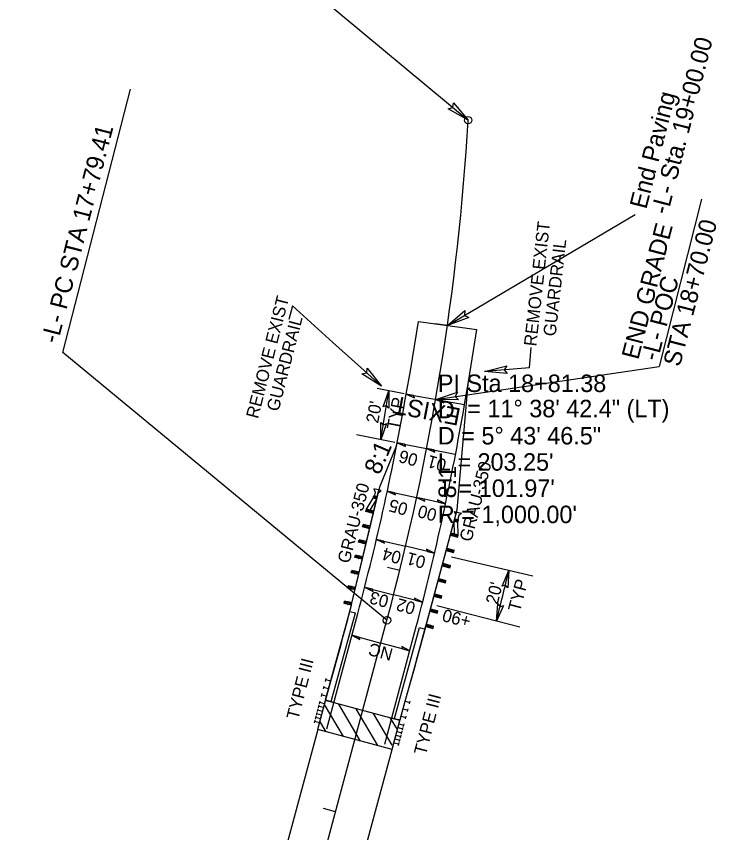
# Model space of a CAD drawing. Extents: x 2078889 to 2079501, y 925860 to 927219.
# Drawn here: x 2079220.3 to 2079500.6, y 926531.6 to 926858.4 of the extents above; entities that cross this region are included whole.
import ezdxf

# ---------------------------------------------------------------- set-up
doc = ezdxf.new("R2010")
doc.units = 0
for name, color, linetype in [('Exist Horizontal Alignment Curve and Spiral Data', 7, 'Continuous'), ('Prop Approach Slab', 7, 'Continuous'), ('Prop Approach Slab Hatching', 7, 'Continuous'), ('Prop Conc Shoulder Berm Gutter', 7, 'Continuous'), ('Prop Dimension Text', 7, 'Continuous'), ('Prop DSN Text', 7, 'Continuous'), ('Prop EOT', 7, 'Continuous'), ('Prop Guardrail', 7, 'Continuous'), ('Prop Guardrail Anchor Unit CELL', 7, 'Continuous'), ('Prop Horizontal Alignment', 7, 'Continuous'), ('Prop Horizontal Alignment Curve and Spiral Data', 7, 'Continuous'), ('Prop Horizontal Alignment Station Label', 7, 'Continuous'), ('Prop Horizontal Alignment Tick Small', 7, 'Continuous'), ('Prop Paved Shoulder', 7, 'Continuous'), ('Prop Roadway Bridge', 7, 'Continuous'), ('Prop Structure Anchor Unit CELL', 7, 'Continuous'), ('Prop Superelevation  Arrow CELL', 7, 'Continuous'), ('Prop Superelevation Label', 7, 'Continuous'), ('Prop Terminator CELL', 7, 'Continuous'), ('Scratch_Level_1', 7, 'Continuous')]:
    doc.layers.add(name, color=color, linetype=linetype)

msp = doc.modelspace()

# ---------------------------------------------------------------- linework, layer by layer
at = {"layer": 'Prop Approach Slab'}
for p, q in [((2079340.91, 926572.87), (2079344.03, 926584.46)), ((2079373.79, 926576.46), (2079344.03, 926584.46)), ((2079370.68, 926564.88), (2079373.79, 926576.46))]:
    msp.add_line(p, q, dxfattribs=at)
at = {"layer": 'Prop Approach Slab Hatching'}
for p, q in [((2079351.2, 926570.11), (2079343.62, 926582.94)), ((2079358.1, 926568.25), (2079349.37, 926583.02)), ((2079365.01, 926566.4), (2079356.28, 926581.17)), ((2079370.71, 926566.58), (2079363.18, 926579.32)), ((2079372.82, 926572.84), (2079370.09, 926577.46)), ((2079344.29, 926571.96), (2079341.8, 926576.18))]:
    msp.add_line(p, q, dxfattribs=at)
at = {"layer": 'Prop Conc Shoulder Berm Gutter'}
for p, q in [((2079344.09, 926584.7), (2079353.76, 926620.16)), ((2079344.09, 926584.7), (2079346.35, 926584.1)), ((2079371.6, 926577.31), (2079373.86, 926576.71))]:
    msp.add_line(p, q, dxfattribs=at)
msp.add_lwpolyline([(2079373.86, 926576.71), (2079375.88, 926584.22), (2079379.59, 926597.39), (2079383.87, 926613.11)], dxfattribs=at)
at = {"layer": 'Prop Dimension Text'}
for p, q in [((2079392.82, 926734.65), (2079467.93, 926779.05)), ((2079330.82, 926742.49), (2079329.41, 926737.03)), ((2079330.82, 926742.49), (2079347, 926727.89)), ((2079347, 926727.89), (2079358.2, 926717.77)), ((2079425.72, 926717.68), (2079426.39, 926725.85)), ((2079358.2, 926717.77), (2079366.4, 926710.38)), ((2079425.72, 926717.68), (2079407.67, 926716.16)), ((2079375.54, 926707.28), (2079364.66, 926709.39)), ((2079371.75, 926687.83), (2079356.43, 926690.81)), ((2079427, 926634.23), (2079394.48, 926641.91)), ((2079421.81, 926613.84), (2079388.56, 926622.39))]:
    msp.add_line(p, q, dxfattribs=at)
for centre, radius, start, end in [((2078435.77, 926855.81), 945.16, 349.8306, 351.03217), ((2078422.74, 926870.98), 1021.93, 345.56858, 346.73523)]:
    msp.add_arc(centre, radius, start, end, dxfattribs=at)
at = {"layer": 'Prop DSN Text'}
msp.add_lwpolyline([(2079416.77, 926715.37), (2079407.67, 926716.16), (2079416.55, 926718.52), (2079415.54, 926716.83)], close=True, dxfattribs=at)
at = {"layer": 'Prop EOT'}
for p, q in [((2079381.26, 926736.3), (2079404.53, 926732.98)), ((2079396.76, 926660.86), (2079401.09, 926711.18)), ((2079344.53, 926573.19), (2079356.92, 926619.31)), ((2079367.71, 926566.97), (2079380.36, 926614.05))]:
    msp.add_line(p, q, dxfattribs=at)
for points in [[(2079376.31, 926707.08), (2079378.1, 926716.55), (2079381.26, 926736.3)], [(2079399.68, 926703.02), (2079401.21, 926712.09), (2079402.29, 926718.73), (2079404.53, 926732.98)]]:
    msp.add_lwpolyline(points, dxfattribs=at)
for centre, radius, start, end in [((2078400.13, 926876.66), 990.8, 344.94546, 350.14494), ((2078395.71, 926874.51), 1018.51, 345.1836, 350.30655)]:
    msp.add_arc(centre, radius, start, end, dxfattribs=at)
at = {"layer": 'Prop Guardrail'}
for centre, radius, start, end in [((2078323.78, 926887.57), 1064.14, 343.88427, 345.58337), ((2078092, 926955.29), 1336.42, 343.87828, 345.2185)]:
    msp.add_arc(centre, radius, start, end, dxfattribs=at)
at = {"layer": 'Prop Guardrail Anchor Unit CELL'}
for p, q in [((2079366.28, 926668.56), (2079363.43, 926669.3)), ((2079363.43, 926669.3), (2079363.96, 926667.95)), ((2079363.96, 926667.95), (2079363.45, 926665.97)), ((2079365.15, 926667.64), (2079366.28, 926668.56)), ((2079353.76, 926620.16), (2079364.7, 926665.61)), ((2079360.46, 926661.08), (2079363.12, 926665.48)), ((2079361.94, 926660.72), (2079364.58, 926665.13)), ((2079363.12, 926665.48), (2079363.36, 926666.45)), ((2079364.81, 926666.1), (2079363.12, 926665.48)), ((2079363.12, 926665.48), (2079363.24, 926665.96)), ((2079364.58, 926665.13), (2079363.12, 926665.48)), ((2079364.81, 926666.1), (2079363.36, 926666.45)), ((2079363.36, 926666.45), (2079364.58, 926665.13)), ((2079363.45, 926665.97), (2079364.04, 926665.81)), ((2079364.04, 926665.81), (2079364.63, 926665.66)), ((2079364.63, 926665.66), (2079365.15, 926667.64)), ((2079360.22, 926660.11), (2079360.46, 926661.08)), ((2079361.94, 926660.72), (2079360.22, 926660.11)), ((2079363.2, 926659.39), (2079360.22, 926660.11)), ((2079363.43, 926660.36), (2079360.46, 926661.08)), ((2079360.46, 926661.08), (2079361.71, 926659.75)), ((2079361.71, 926659.75), (2079361.94, 926660.72)), ((2079361.71, 926659.75), (2079363.43, 926660.36)), ((2079363.2, 926659.39), (2079361.94, 926660.72)), ((2079396.22, 926658.79), (2079395.66, 926660.14)), ((2079395.66, 926660.14), (2079398.52, 926659.43)), ((2079395.72, 926656.81), (2079396.22, 926658.79)), ((2079397.4, 926658.5), (2079396.9, 926656.51)), ((2079398.52, 926659.43), (2079397.4, 926658.5)), ((2079358.81, 926653.96), (2079359.04, 926654.94)), ((2079361.96, 926654.23), (2079359.04, 926654.94)), ((2079359.04, 926654.94), (2079360.27, 926653.61)), ((2079383.49, 926611.65), (2079395.64, 926656.8)), ((2079397.22, 926656.89), (2079395.51, 926656.31)), ((2079395.51, 926656.31), (2079396.96, 926655.92)), ((2079395.71, 926651.18), (2079395.51, 926656.31)), ((2079396.31, 926656.66), (2079395.72, 926656.81)), ((2079395.77, 926657.28), (2079397.22, 926656.89)), ((2079395.77, 926657.28), (2079396.96, 926655.92)), ((2079396.9, 926656.51), (2079396.31, 926656.66)), ((2079396.96, 926655.92), (2079397.22, 926656.89)), ((2079396.96, 926655.92), (2079397.09, 926656.41)), ((2079397.19, 926650.79), (2079396.96, 926655.92)), ((2079360.5, 926654.59), (2079358.81, 926653.96)), ((2079361.73, 926653.26), (2079358.81, 926653.96)), ((2079360.27, 926653.61), (2079360.5, 926654.59)), ((2079360.27, 926653.61), (2079361.96, 926654.23)), ((2079361.73, 926653.26), (2079360.5, 926654.59)), ((2079394.23, 926651.58), (2079397.19, 926650.79)), ((2079395.45, 926650.22), (2079394.23, 926651.58)), ((2079357.2, 926647.87), (2079357.44, 926648.84)), ((2079358.96, 926648.47), (2079357.2, 926647.87)), ((2079360.49, 926648.11), (2079357.44, 926648.84)), ((2079357.44, 926648.84), (2079358.73, 926647.5)), ((2079358.73, 926647.5), (2079358.96, 926648.47)), ((2079360.25, 926647.14), (2079358.96, 926648.47)), ((2079393.97, 926650.62), (2079395.71, 926651.18)), ((2079393.97, 926650.62), (2079396.93, 926649.82)), ((2079395.45, 926650.22), (2079395.71, 926651.18)), ((2079397.19, 926650.79), (2079395.45, 926650.22)), ((2079395.71, 926651.18), (2079396.93, 926649.82)), ((2079396.93, 926649.82), (2079397.19, 926650.79)), ((2079360.25, 926647.14), (2079357.2, 926647.87)), ((2079358.73, 926647.5), (2079360.49, 926648.11)), ((2079392.34, 926644.53), (2079394.05, 926645.11)), ((2079392.6, 926645.5), (2079395.49, 926644.72)), ((2079393.79, 926644.14), (2079392.6, 926645.5)), ((2079393.79, 926644.14), (2079394.05, 926645.11)), ((2079394.05, 926645.11), (2079395.23, 926643.75)), ((2079355.83, 926641.72), (2079356.06, 926642.69)), ((2079357.54, 926642.34), (2079355.83, 926641.72)), ((2079358.78, 926641.01), (2079355.83, 926641.72)), ((2079359.01, 926641.98), (2079356.06, 926642.69)), ((2079356.06, 926642.69), (2079357.3, 926641.36)), ((2079357.3, 926641.36), (2079357.54, 926642.34)), ((2079357.3, 926641.36), (2079359.01, 926641.98)), ((2079358.78, 926641.01), (2079357.54, 926642.34)), ((2079358.78, 926641.01), (2079359.01, 926641.98)), ((2079392.34, 926644.53), (2079395.23, 926643.75)), ((2079395.49, 926644.72), (2079393.79, 926644.14)), ((2079395.23, 926643.75), (2079395.49, 926644.72)), ((2079390.7, 926638.45), (2079392.47, 926639)), ((2079390.7, 926638.45), (2079393.73, 926637.63)), ((2079390.96, 926639.41), (2079393.99, 926638.6)), ((2079392.21, 926638.04), (2079390.96, 926639.41)), ((2079392.21, 926638.04), (2079392.47, 926639)), ((2079393.99, 926638.6), (2079392.21, 926638.04)), ((2079392.47, 926639), (2079393.73, 926637.63)), ((2079393.73, 926637.63), (2079393.99, 926638.6)), ((2079354.34, 926635.6), (2079354.57, 926636.57)), ((2079356.06, 926636.21), (2079354.34, 926635.6)), ((2079357.3, 926634.88), (2079354.34, 926635.6)), ((2079357.54, 926635.86), (2079354.57, 926636.57)), ((2079354.57, 926636.57), (2079355.82, 926635.24)), ((2079355.82, 926635.24), (2079356.06, 926636.21)), ((2079355.82, 926635.24), (2079357.54, 926635.86)), ((2079357.3, 926634.88), (2079356.06, 926636.21)), ((2079389.06, 926632.36), (2079389.32, 926633.33)), ((2079389.06, 926632.36), (2079390.79, 926632.93)), ((2079389.06, 926632.36), (2079391.99, 926631.57)), ((2079389.32, 926633.33), (2079392.25, 926632.54)), ((2079390.53, 926631.97), (2079389.32, 926633.33)), ((2079390.53, 926631.97), (2079390.79, 926632.93)), ((2079392.25, 926632.54), (2079390.53, 926631.97)), ((2079390.79, 926632.93), (2079391.99, 926631.57)), ((2079391.99, 926631.57), (2079392.25, 926632.54)), ((2079352.86, 926629.47), (2079353.1, 926630.44)), ((2079354.58, 926630.09), (2079352.86, 926629.47)), ((2079355.83, 926628.76), (2079352.86, 926629.47)), ((2079356.06, 926629.73), (2079353.1, 926630.44)), ((2079353.1, 926630.44), (2079354.35, 926629.11)), ((2079354.35, 926629.11), (2079354.58, 926630.09)), ((2079354.35, 926629.11), (2079356.06, 926629.73)), ((2079355.83, 926628.76), (2079354.58, 926630.09)), ((2079387.42, 926626.28), (2079389.16, 926626.85)), ((2079387.42, 926626.28), (2079390.37, 926625.48)), ((2079387.68, 926627.24), (2079390.63, 926626.45)), ((2079388.9, 926625.88), (2079387.68, 926627.24)), ((2079388.9, 926625.88), (2079389.16, 926626.85)), ((2079390.63, 926626.45), (2079388.9, 926625.88)), ((2079389.16, 926626.85), (2079390.37, 926625.48)), ((2079390.37, 926625.48), (2079390.63, 926626.45)), ((2079351.44, 926623.33), (2079351.67, 926624.3)), ((2079353.13, 926623.95), (2079351.44, 926623.33)), ((2079354.36, 926622.63), (2079351.44, 926623.33)), ((2079354.59, 926623.6), (2079351.67, 926624.3)), ((2079351.67, 926624.3), (2079352.9, 926622.98)), ((2079352.9, 926622.98), (2079353.13, 926623.95)), ((2079352.9, 926622.98), (2079354.59, 926623.6)), ((2079354.59, 926623.6), (2079353.13, 926623.95)), ((2079353.13, 926623.95), (2079354.36, 926622.63)), ((2079354.36, 926622.63), (2079354.59, 926623.6)), ((2079385.79, 926620.19), (2079387.52, 926620.76)), ((2079385.79, 926620.19), (2079388.73, 926619.4)), ((2079386.05, 926621.16), (2079388.99, 926620.36)), ((2079387.26, 926619.8), (2079386.05, 926621.16)), ((2079387.26, 926619.8), (2079387.52, 926620.76)), ((2079388.99, 926620.36), (2079387.26, 926619.8)), ((2079387.52, 926620.76), (2079388.73, 926619.4)), ((2079388.73, 926619.4), (2079388.99, 926620.36)), ((2079384.15, 926614.11), (2079384.41, 926615.07)), ((2079385.86, 926614.68), (2079384.15, 926614.11)), ((2079384.15, 926614.11), (2079387.05, 926613.33)), ((2079384.41, 926615.07), (2079387.31, 926614.29)), ((2079384.41, 926615.07), (2079385.86, 926614.68)), ((2079385.6, 926613.72), (2079384.41, 926615.07)), ((2079385.6, 926613.72), (2079385.86, 926614.68)), ((2079387.31, 926614.29), (2079385.6, 926613.72)), ((2079385.86, 926614.68), (2079387.05, 926613.33)), ((2079387.05, 926613.33), (2079387.31, 926614.29))]:
    msp.add_line(p, q, dxfattribs=at)
at = {"layer": 'Prop Horizontal Alignment'}
msp.add_line((2079220.28, 926064.49), (2079368.62, 926616.59), dxfattribs=at)
msp.add_arc((2078402.86, 926876.05), 1000, 344.96174, 356.60686, dxfattribs=at)
at = {"layer": 'Prop Horizontal Alignment Curve and Spiral Data'}
msp.add_line((2079238.84, 926723.88), (2079265.92, 926829.22), dxfattribs=at)
at = {"layer": 'Prop Horizontal Alignment Station Label'}
for p, q in [((2079279.57, 926918.1), (2079401.11, 926816.87)), ((2079494.47, 926785.26), (2079477.57, 926718.27)), ((2079368.62, 926616.59), (2079238.84, 926723.88)), ((2079388.13, 926705.02), (2079477.57, 926718.27))]:
    msp.add_line(p, q, dxfattribs=at)
for centre in [(2079401.11, 926816.87), (2079368.62, 926616.59)]:
    msp.add_circle(centre, 1.5, dxfattribs=at)
at = {"layer": 'Prop Horizontal Alignment Tick Small'}
for p, q in [((2079392.82, 926734.65), (2079387.87, 926735.36)), ((2079373.75, 926636.53), (2079368.9, 926637.73)), ((2079348.01, 926539.9), (2079343.18, 926541.2))]:
    msp.add_line(p, q, dxfattribs=at)
at = {"layer": 'Prop Paved Shoulder'}
for p, q in [((2079365.75, 926670.05), (2079372.56, 926686.78)), ((2079353.76, 926620.16), (2079365.75, 926670.05)), ((2079383.87, 926613.11), (2079396.76, 926660.86)), ((2079346.35, 926584.1), (2079356.01, 926619.55)), ((2079353.76, 926620.16), (2079356.01, 926619.55)), ((2079371.6, 926577.31), (2079381.61, 926613.72)), ((2079381.61, 926613.72), (2079383.87, 926613.11)), ((2079346.35, 926584.1), (2079347.37, 926583.82)), ((2079370.56, 926577.59), (2079371.6, 926577.31))]:
    msp.add_line(p, q, dxfattribs=at)
at = {"layer": 'Prop Roadway Bridge'}
for p, q in [((2079340.91, 926572.87), (2079298.1, 926413.52)), ((2079370.68, 926564.88), (2079340.91, 926572.87)), ((2079327.87, 926405.53), (2079370.68, 926564.88))]:
    msp.add_line(p, q, dxfattribs=at)
at = {"layer": 'Prop Structure Anchor Unit CELL'}
for p, q in [((2079344.02, 926592.15), (2079344.32, 926593.26)), ((2079346.1, 926592.19), (2079344.17, 926592.71)), ((2079341.24, 926574.08), (2079346.1, 926592.19)), ((2079343.21, 926589.14), (2079343.51, 926590.24)), ((2079345.29, 926589.17), (2079343.36, 926589.69)), ((2079342.4, 926586.12), (2079342.7, 926587.22)), ((2079344.48, 926586.15), (2079342.55, 926586.67)), ((2079341.59, 926583.1), (2079341.89, 926584.21)), ((2079343.67, 926583.13), (2079341.74, 926583.65)), ((2079371, 926566.08), (2079375.87, 926584.19)), ((2079375.87, 926584.19), (2079377.8, 926583.67)), ((2079377.65, 926583.12), (2079377.95, 926584.22)), ((2079340.37, 926578.57), (2079340.67, 926579.68)), ((2079340.78, 926580.08), (2079341.08, 926581.19)), ((2079342.86, 926580.12), (2079340.93, 926580.63)), ((2079341.18, 926581.59), (2079341.48, 926582.7)), ((2079343.26, 926581.62), (2079341.33, 926582.14)), ((2079375.06, 926581.17), (2079376.99, 926580.65)), ((2079376.84, 926580.1), (2079377.14, 926581.21)), ((2079339.56, 926575.55), (2079339.86, 926576.66)), ((2079339.97, 926577.06), (2079340.27, 926578.17)), ((2079342.05, 926577.1), (2079340.12, 926577.62)), ((2079342.45, 926578.61), (2079340.52, 926579.13)), ((2079374.25, 926578.15), (2079376.18, 926577.64)), ((2079376.03, 926577.08), (2079376.33, 926578.19)), ((2079341.64, 926575.59), (2079339.71, 926576.11)), ((2079373.03, 926573.63), (2079374.96, 926573.11)), ((2079373.43, 926575.14), (2079375.37, 926574.62)), ((2079374.81, 926572.56), (2079375.11, 926573.66)), ((2079375.22, 926574.06), (2079375.51, 926575.17)), ((2079372.22, 926570.61), (2079374.15, 926570.09)), ((2079372.62, 926572.12), (2079374.56, 926571.6)), ((2079374, 926569.54), (2079374.3, 926570.64)), ((2079374.41, 926571.05), (2079374.7, 926572.15)), ((2079371.41, 926567.59), (2079373.34, 926567.07)), ((2079371.81, 926569.1), (2079373.74, 926568.58)), ((2079373.19, 926566.52), (2079373.49, 926567.63)), ((2079373.6, 926568.03), (2079373.89, 926569.13))]:
    msp.add_line(p, q, dxfattribs=at)
at = {"layer": 'Prop Superelevation  Arrow CELL'}
for p, q in [((2079376.31, 926707.08), (2079390.1, 926704.68)), ((2079388.13, 926705.02), (2079399.68, 926703.02)), ((2079372.73, 926687.64), (2079384.51, 926685.35)), ((2079384.51, 926685.35), (2079395.99, 926683.12)), ((2079368.77, 926668.28), (2079380.5, 926665.76)), ((2079392.08, 926663.27), (2079381.83, 926665.47)), ((2079364.42, 926649.01), (2079376.1, 926646.25)), ((2079387.68, 926643.52), (2079376.1, 926646.25)), ((2079359.96, 926629.75), (2079371.31, 926626.83)), ((2079382.81, 926623.87), (2079371.31, 926626.83)), ((2079354.59, 926610.62), (2079366.17, 926607.5)), ((2079377.76, 926604.39), (2079366.17, 926607.5))]:
    msp.add_line(p, q, dxfattribs=at)
for points in [[(2079376.31, 926707.08), (2079379.62, 926705.69), (2079379.21, 926706.57)], [(2079388.13, 926705.02), (2079391.44, 926703.64), (2079391.03, 926704.52)], [(2079372.73, 926687.64), (2079376.01, 926686.19), (2079375.63, 926687.08)], [(2079384.51, 926685.35), (2079387.79, 926683.9), (2079387.41, 926684.79)], [(2079368.77, 926668.28), (2079372.02, 926666.77), (2079371.65, 926667.66)], [(2079380.5, 926665.76), (2079383.75, 926664.24), (2079383.38, 926665.14)], [(2079392.08, 926663.27), (2079388.82, 926664.79), (2079389.19, 926663.89)], [(2079364.42, 926649.01), (2079367.64, 926647.43), (2079367.29, 926648.33)], [(2079387.68, 926643.52), (2079384.46, 926645.1), (2079384.81, 926644.19)], [(2079359.96, 926629.75), (2079363.15, 926628.11), (2079362.82, 926629.02)], [(2079382.81, 926623.87), (2079379.62, 926625.52), (2079379.96, 926624.61)], [(2079354.59, 926610.62), (2079357.76, 926608.94), (2079357.43, 926609.85)], [(2079377.76, 926604.39), (2079374.59, 926606.07), (2079374.91, 926605.16)]]:
    msp.add_lwpolyline(points, close=True, dxfattribs=at)
at = {"layer": 'Prop Terminator CELL'}
for points in [[(2079395.21, 926823.84), (2079401.11, 926816.87), (2079393.15, 926821.45), (2079395.05, 926821.94)], [(2079401.36, 926737.89), (2079392.82, 926734.65), (2079399.8, 926740.63), (2079399.62, 926738.66)], [(2079360.75, 926717.56), (2079366.4, 926710.38), (2079358.61, 926715.26), (2079360.53, 926715.67)], [(2079367.11, 926702.01), (2079369.36, 926708.48), (2079369.44, 926701.59), (2079368.39, 926702.64)], [(2079397.26, 926704.81), (2079388.13, 926705.02), (2079396.85, 926707.93), (2079395.94, 926706.18)], [(2079368.45, 926695.35), (2079366.12, 926688.91), (2079366.14, 926695.8), (2079367.17, 926694.74)], [(2079414.72, 926630.2), (2079417.4, 926636.5), (2079417.01, 926629.62), (2079416.04, 926630.73)], [(2079415.23, 926622.54), (2079412.42, 926616.29), (2079412.95, 926623.17), (2079413.9, 926622.03)]]:
    msp.add_lwpolyline(points, close=True, dxfattribs=at)
at = {"layer": 'Scratch_Level_1'}
for p, q in [((2079353.76, 926620.16), (2079365.43, 926668.82)), ((2079383.49, 926611.65), (2079396.52, 926659.92)), ((2079346.1, 926592.19), (2079354.41, 926622.63)), ((2079341.24, 926574.08), (2079346.1, 926592.19)), ((2079371, 926566.08), (2079375.87, 926584.19))]:
    msp.add_line(p, q, dxfattribs=at)
msp.add_lwpolyline([(2079375.87, 926584.19), (2079375.87, 926584.19), (2079379.75, 926597.92), (2079384.2, 926614.32), (2079384.2, 926614.32), (2079384.2, 926614.32), (2079384.2, 926614.32), (2079384.05, 926613.79)], dxfattribs=at)

# ---------------------------------------------------------------- texts
at = {"layer": 'Exist Horizontal Alignment Curve and Spiral Data'}
for s, p in [('PI Sta 18+81.38', (2079389, 926708)), ('D', (2079389, 926697.5)), ('= 11%%d 38\' 42.4" (LT)', (2079400.77, 926697.89)), ('D = 5%%d 43\' 46.5"', (2079389, 926687)), ("L = 203.25'", (2079389, 926676.5)), ("T = 101.97'", (2079389, 926666)), ("R = 1,000.00'", (2079389, 926655.5))]:
    msp.add_text(s, height=7, dxfattribs=at).set_placement(p)
at = {"layer": 'Prop Dimension Text'}
for s, height, rotation, p in [('REMOVE EXIST', 5, 83.6568, (2079428.38, 926726.15)), ('END GRADE', 7, 75.5414, (2079469.2, 926720.65)), ('STA 18+70.00', 7, 75.5414, (2079485.86, 926717.83)), ('GUARDRAIL', 5, 83.6568, (2079436.12, 926730.13)), ('-L- POC ', 7, 75.5414, (2079476.97, 926720.12)), ('REMOVE EXIST', 5, 75.5809, (2079316.99, 926697.08)), ('GUARDRAIL', 5, 75.5809, (2079325.21, 926699.94)), ("20'", 5, 79.1563, (2079365.07, 926695.24)), ('TYP', 5, 79.3628, (2079373.38, 926692.55)), ('EXIST', 7, 169.0037, (2079398.54, 926701.34)), ("20'", 5, 76.3097, (2079412.94, 926622.65)), ('TYP', 5, 75.1911, (2079421.81, 926619.7)), ('+90', 5, 165.5809, (2079402.59, 926618.38))]:
    msp.add_text(s, height=height, rotation=rotation, dxfattribs=at).set_placement(p)
at = {"layer": 'Prop DSN Text'}
for s, rotation, p in [('-L- Sta. 19+00.00', 75.5812, (2079481, 926778.74)), ('End Paving', 75.5812, (2079472.41, 926780.95)), ('8:1', 66.8169, (2079365.65, 926674.49)), ('8:1', 89.6276, (2079396.24, 926665.42))]:
    msp.add_text(s, height=7, rotation=rotation, dxfattribs=at).set_placement(p)
at = {"layer": 'Prop Guardrail Anchor Unit CELL'}
for s, p in [('GRAU-350', (2079402.38, 926647.75)), ('GRAU-350', (2079353.58, 926639.09)), ('TYPE III', (2079333.15, 926576.53)), ('TYPE III', (2079384.18, 926562.32))]:
    msp.add_text(s, height=5, rotation=75.5809, dxfattribs=at).set_placement(p)
at = {"layer": 'Prop Horizontal Alignment Station Label'}
msp.add_text('-L- PC STA 17+79.41', height=7, rotation=75.5809, dxfattribs=at).set_placement((2079236.83, 926727.09))
at = {"layer": 'Prop Superelevation Label'}
for s, p in [('06', (2079381.41, 926682.92)), ('01', (2079392.8, 926680.83)), ('05', (2079377.39, 926663.25)), ('00', (2079388.99, 926660.91)), ('04', (2079374.76, 926643.83)), ('01', (2079384.52, 926642)), ('03', (2079369.72, 926626.33)), ('02', (2079380.41, 926623.56)), ('NC', (2079371.41, 926605.09))]:
    msp.add_text(s, height=5, rotation=164.7434, dxfattribs=at).set_placement(p)

doc.saveas('drawing.dxf')
